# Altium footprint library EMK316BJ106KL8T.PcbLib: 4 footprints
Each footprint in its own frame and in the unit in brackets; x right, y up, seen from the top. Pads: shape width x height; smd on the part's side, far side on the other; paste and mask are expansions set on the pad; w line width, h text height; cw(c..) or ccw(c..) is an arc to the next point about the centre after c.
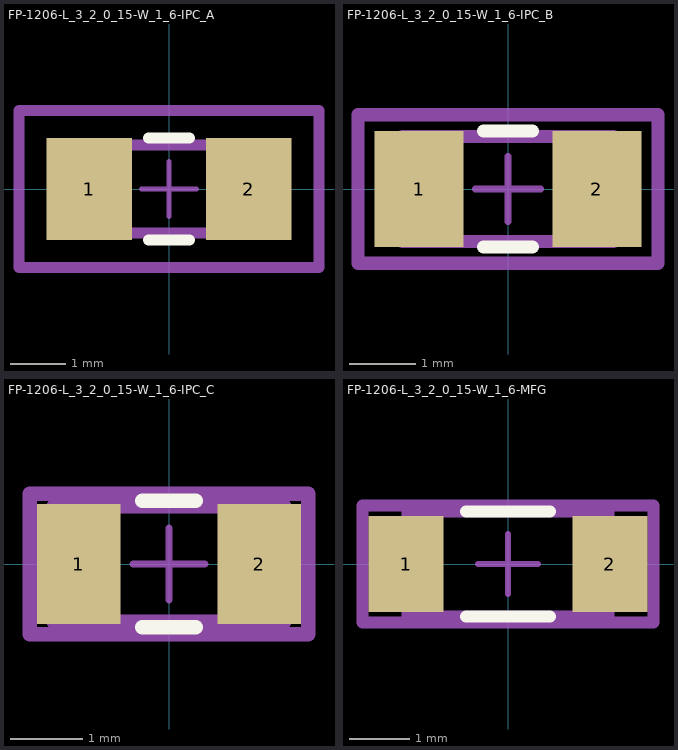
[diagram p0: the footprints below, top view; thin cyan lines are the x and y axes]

## FP-1206-L_3_2_0_15-W_1_6-IPC_A [mm]
pads (2):
  rect 1.555x1.858 smd paste+0 mask+0: 1(-1.451,0) 2(1.451,0)
Top Overlay:
  lines w0.2: -0.374,-0.929 0.374,-0.929 ; -0.374,0.929 0.374,0.929
Mechanical 5:
  lines w0.2: -2.729,-1.429 2.729,-1.429 2.729,1.429 -2.729,1.429 -2.729,-1.429
  text ".Designator" at 0,0.188 h1
Mechanical 13:
  lines w0.2: -1.6,-0.8 1.6,-0.8 1.6,0.8 -1.6,0.8 -1.6,-0.8
Mechanical 15:
  lines w0.2: -2.729,-1.429 2.729,-1.429 2.729,1.429 -2.729,1.429 -2.729,-1.429
Mechanical 16:
  lines w0.1: -0.5,0 0.5,0 ; 0,-0.5 0,0.5
3D body "Cap_Taiyo_Yuden_TMF316B7104KLHT_eec.STEP": height 0.25, standoff 0, extent -2.729,-1.429 2.729,1.429

## FP-1206-L_3_2_0_15-W_1_6-IPC_B [mm]
pads (2):
  rect 1.355x1.758 smd paste+0 mask+0: 1(-1.351,0) 2(1.351,0)
Top Overlay:
  lines w0.2: -0.374,-0.879 0.374,-0.879 ; -0.374,0.879 0.374,0.879
Mechanical 5:
  lines w0.2: -2.279,-1.129 2.279,-1.129 2.279,1.129 -2.279,1.129 -2.279,-1.129
  text ".Designator" at 0,0.188 h1
Mechanical 13:
  lines w0.2: -1.6,-0.8 1.6,-0.8 1.6,0.8 -1.6,0.8 -1.6,-0.8
Mechanical 15:
  lines w0.2: -2.279,-1.129 2.279,-1.129 2.279,1.129 -2.279,1.129 -2.279,-1.129
Mechanical 16:
  lines w0.1: -0.5,0 0.5,0 ; 0,-0.5 0,0.5
3D body "Cap_Taiyo_Yuden_TMF316B7104KLHT_eec.STEP": height 0.25, standoff 0, extent -2.279,-1.129 2.279,1.129

## FP-1206-L_3_2_0_15-W_1_6-IPC_C [mm]
pads (2):
  rect 1.155x1.658 smd paste+0 mask+0: 1(-1.251,0) 2(1.251,0)
Top Overlay:
  lines w0.2: -0.374,-0.875 0.374,-0.875 ; -0.374,0.875 0.374,0.875
Mechanical 5:
  lines w0.2: -1.929,-0.975 1.929,-0.975 1.929,0.975 -1.929,0.975 -1.929,-0.975
  text ".Designator" at 0,0.188 h1
Mechanical 13:
  lines w0.2: -1.6,-0.8 1.6,-0.8 1.6,0.8 -1.6,0.8 -1.6,-0.8
Mechanical 15:
  lines w0.2: -1.929,-0.975 1.929,-0.975 1.929,0.975 -1.929,0.975 -1.929,-0.975
Mechanical 16:
  lines w0.1: -0.5,0 0.5,0 ; 0,-0.5 0,0.5
3D body "Cap_Taiyo_Yuden_TMF316B7104KLHT_eec.STEP": height 0.25, standoff 0, extent -1.929,-0.975 1.929,0.975

## FP-1206-L_3_2_0_15-W_1_6-MFG [mm]
pads (2):
  rect 1.25x1.6 smd paste+0 mask+0: 1(-1.7,0) 2(1.7,0)
Top Overlay:
  lines w0.2: -0.7,-0.875 0.7,-0.875 ; -0.7,0.875 0.7,0.875
Mechanical 5:
  lines w0.2: -2.425,-0.975 2.425,-0.975 2.425,0.975 -2.425,0.975 -2.425,-0.975
  text ".Designator" at 0,0.188 h1
Mechanical 13:
  lines w0.2: -1.675,-0.875 1.675,-0.875 1.675,0.875 -1.675,0.875 -1.675,-0.875
Mechanical 15:
  lines w0.2: -2.425,-0.975 2.425,-0.975 2.425,0.975 -2.425,0.975 -2.425,-0.975
Mechanical 16:
  lines w0.1: -0.5,0 0.5,0 ; 0,-0.5 0,0.5
3D body "Cap_Taiyo_Yuden_TMF316B7104KLHT_eec.STEP": height 0.25, standoff 0, extent -2.425,-0.975 2.425,0.975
